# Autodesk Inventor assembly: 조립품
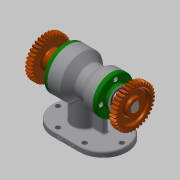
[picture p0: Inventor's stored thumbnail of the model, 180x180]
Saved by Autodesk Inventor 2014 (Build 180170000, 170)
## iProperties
Created: 2020-01
Part Number: 조립품
Document SubType Name: Assembly
Designer: kh
Author: kh
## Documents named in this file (13)
- C:\Users\kh\Desktop\700104V1028\조립품.iam
- C:\Users\kh\Desktop\700104V1028\본체.ipt
- C:\Users\kh\Desktop\700104V1028\뒤커버.ipt
- C:\Users\kh\Desktop\700104V1028\멈춤나사 M3.ipt
- C:\Users\kh\Desktop\700104V1028\베어링 6203.ipt
- C:\Users\kh\Desktop\700104V1028\베어링 6205.ipt
- C:\Users\kh\Desktop\700104V1028\볼트 M4.ipt
- C:\Users\kh\Desktop\700104V1028\스퍼기어.ipt
- C:\Users\kh\Desktop\700104V1028\앞커버.ipt
- C:\Users\kh\Desktop\700104V1028\오일 실 17 30 8.ipt
- C:\Users\kh\Desktop\700104V1028\오일 실 25 38 8.ipt
- C:\Users\kh\Desktop\700104V1028\축.ipt
- C:\Users\kh\Desktop\700104V1028\키 5 x 5 x 18.ipt
